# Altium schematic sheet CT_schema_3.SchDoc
size 352 x 211 mm
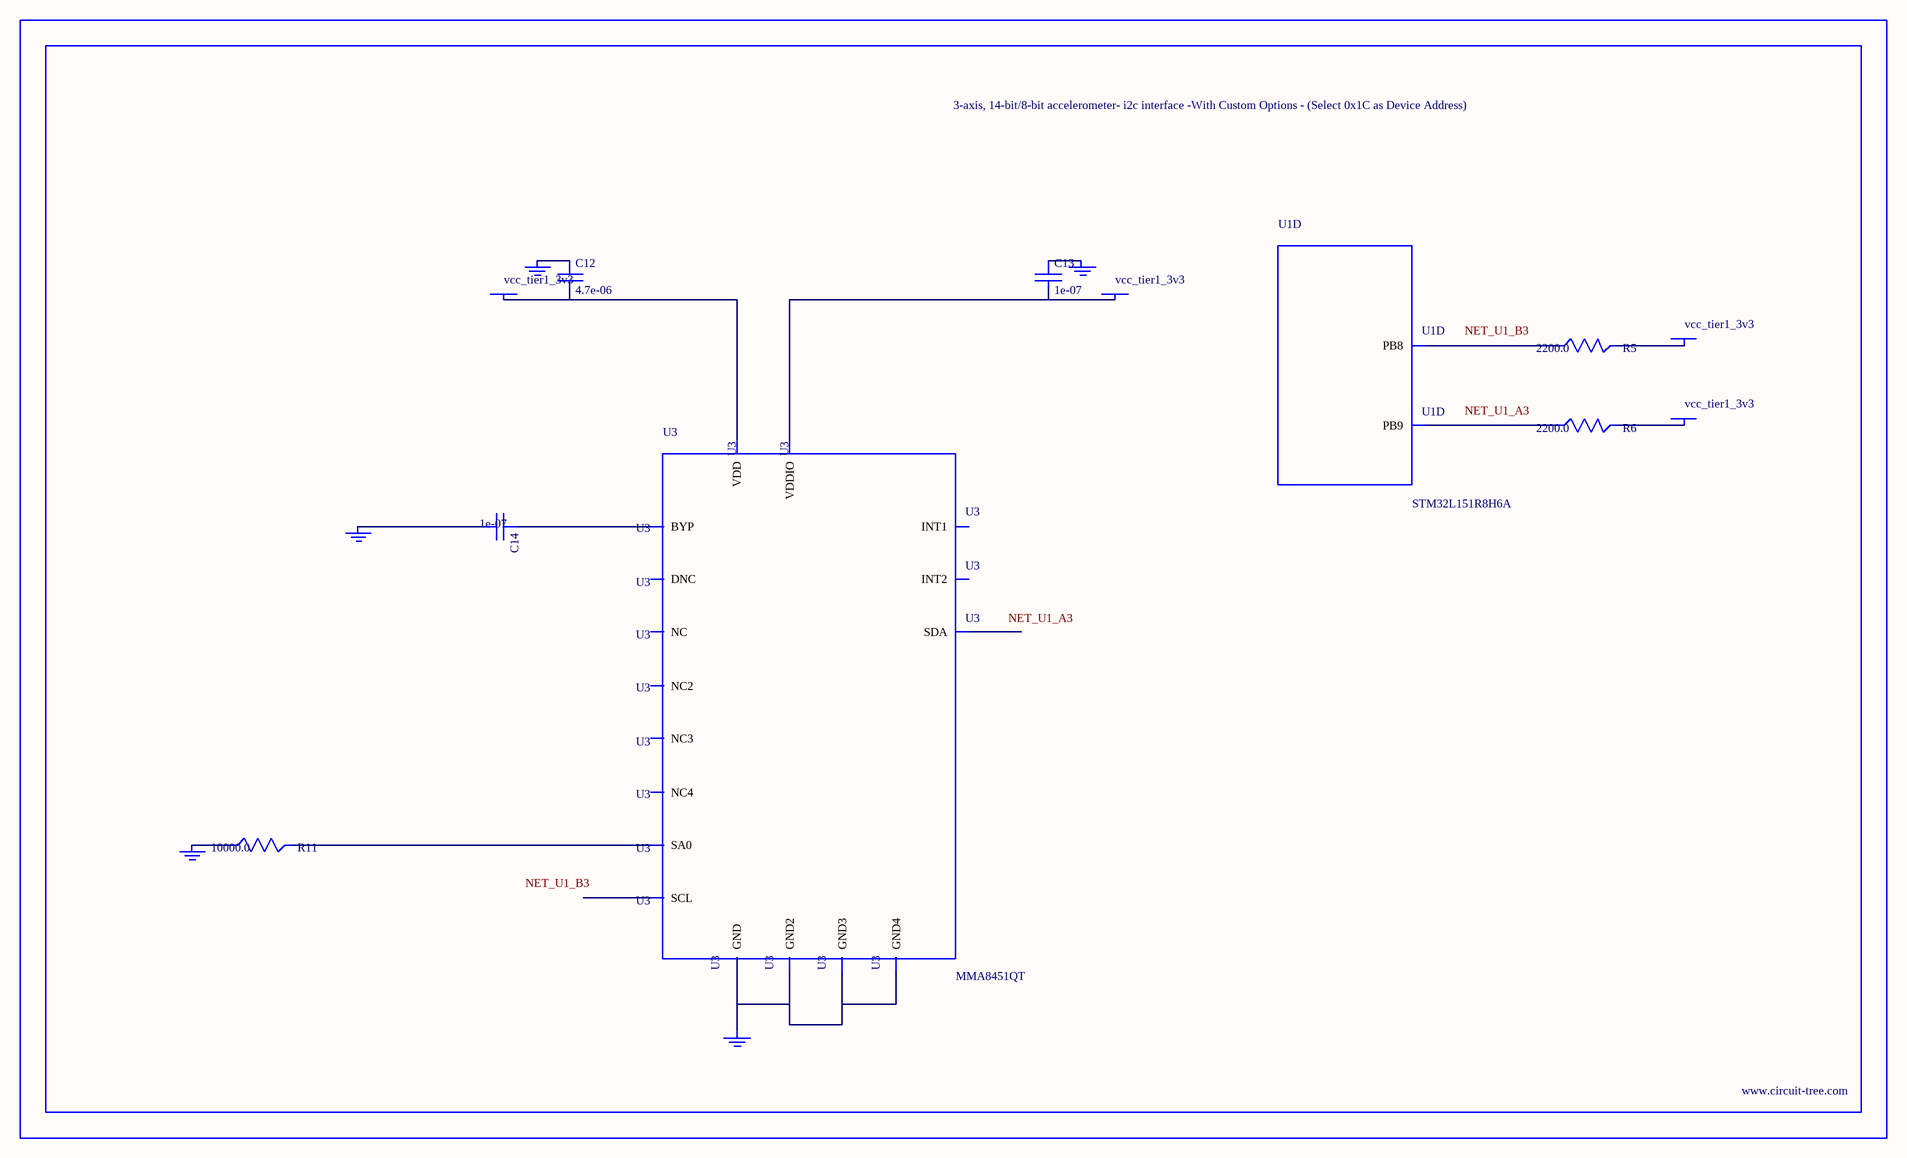
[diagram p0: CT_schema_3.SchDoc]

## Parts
BORDER2  (no value)
C12  4.7e-06  [C0805]
C13  1e-07  [C0402]
C14  1e-07  [C0402]
GND_INSTANCE_2_0  (no value)
GND_INSTANCE_2_1  (no value)
GND_INSTANCE_2_2  (no value)
GND_INSTANCE_2_3  (no value)
GND_INSTANCE_2_4  (no value)
POWER_INSTANCE_2_0  vcc_tier1_3v3
POWER_INSTANCE_2_1  vcc_tier1_3v3
POWER_INSTANCE_2_2  vcc_tier1_3v3
POWER_INSTANCE_2_3  vcc_tier1_3v3
R5  2200.0  [R0603]
R6  2200.0  [R0603]
R11  10000.0  [R0603]
U1  STM32L151R8H6A  [TFBGA64]  (part D of 7)
U3  MMA8451QT  [QFN-16]

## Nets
NetC12_1: C12.1 GND_INSTANCE_2_3.0(GND)
NetC12_2: C12.2 POWER_INSTANCE_2_1.0(PWR) U3.14(VDD)
NetC13_1: C13.1 GND_INSTANCE_2_0.0(GND)
NetC13_2: C13.2 POWER_INSTANCE_2_0.0(PWR) U3.1(VDDIO)
NetC14_1: C14.1 U3.2(BYP)
NetC14_2: C14.2 GND_INSTANCE_2_1.0(GND)
NetGND_INSTANCE_2_2_0: GND_INSTANCE_2_2.0(GND) R11.1
NetGND_INSTANCE_2_4_0: GND_INSTANCE_2_4.0(GND) U3.5(GND) U3.10(GND2) U3.12(GND3) U3.17(GND4)
NetPOWER_INSTANCE_2_2_0: POWER_INSTANCE_2_2.0(PWR) R5.2
NetPOWER_INSTANCE_2_3_0: POWER_INSTANCE_2_3.0(PWR) R6.2
NetR5_1: R5.1 U1.B3(PB8)
NetR6_1: R6.1 U1.A3(PB9)
NetR11_2: R11.2 U3.7(SA0)

Not connected (* = marked no-connect by the designer): U3 3(DNC) 4(SCL) 6(SDA) 8(NC) 9(INT2) 11(INT1) 13(NC2) 15(NC3) 16(NC4)

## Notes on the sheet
- Labels drawn without touching a wire or pin: NET_U1_A3, NET_U1_B3

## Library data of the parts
BORDER2 = BORDER_PAGE2
C12 = C0805C475K4RACTU
C13 C14 = C0402C104K3RACTU
GND_INSTANCE_2_0-GND_INSTANCE_2_4 = GND
POWER_INSTANCE_2_0-POWER_INSTANCE_2_3 = PWR
R5 R6 = RC0603JR-072K2L
R11 = RC0603JR-0710KL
